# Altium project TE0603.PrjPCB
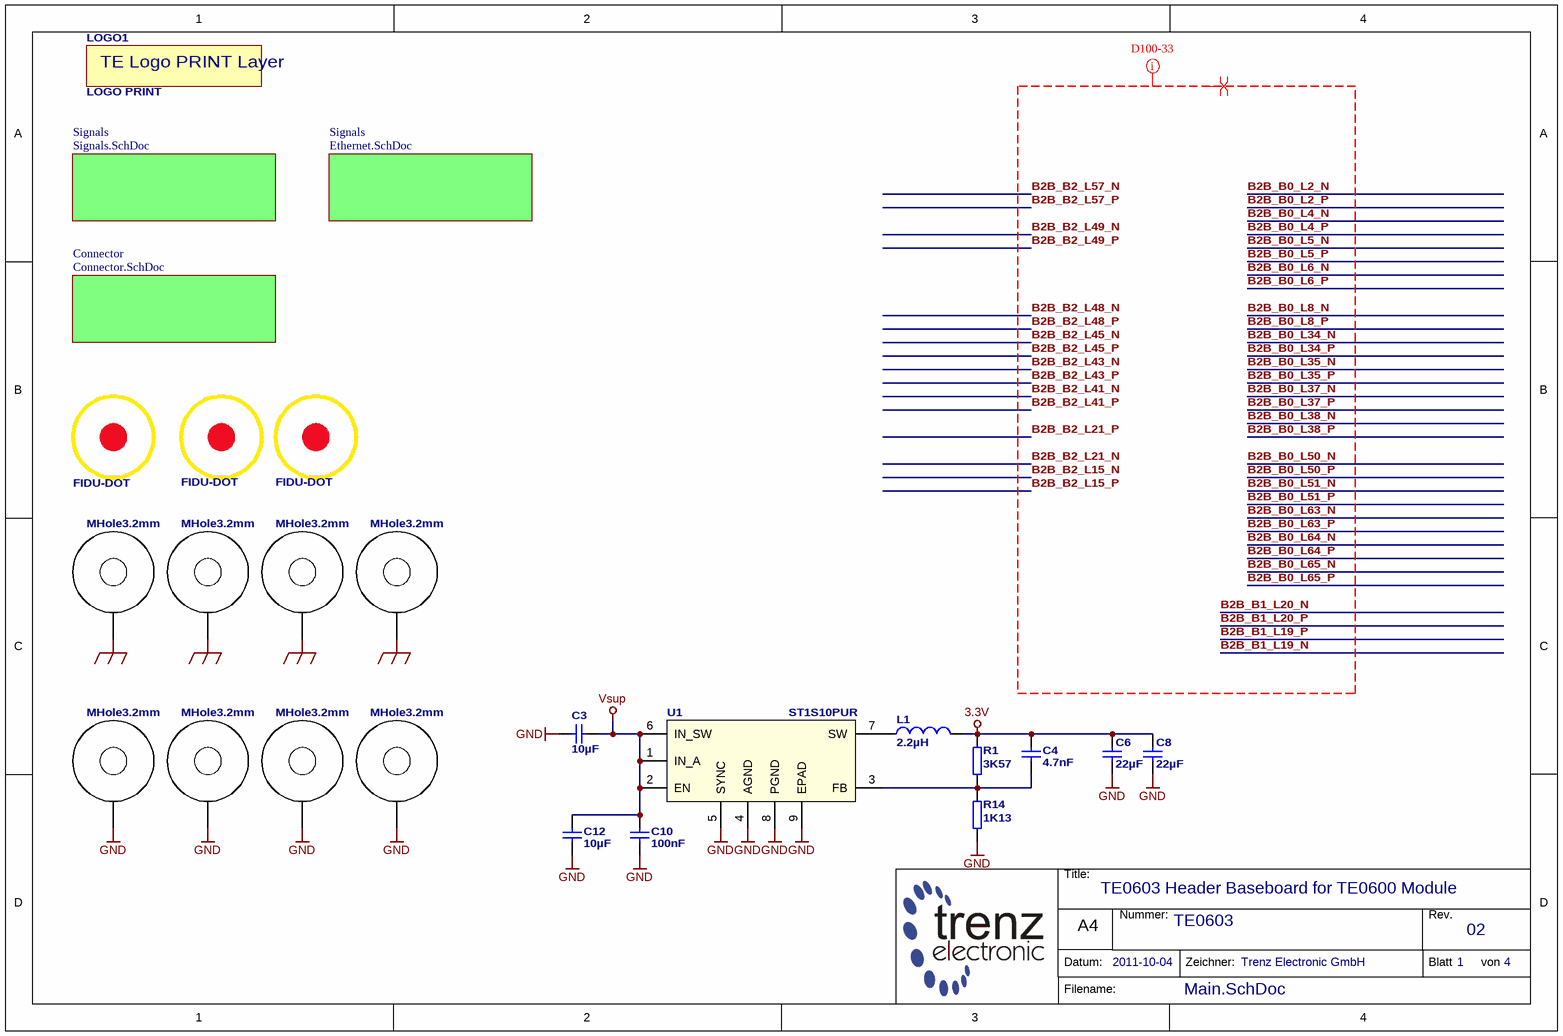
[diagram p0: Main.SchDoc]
4 sheets, 86 parts. Net scope: global (net labels, ports and power ports of the same name join across sheets).
Board file: TE0603.PcbDoc
Sheets:
  Main.SchDoc
    Connector = Connector.SchDoc
    Signals = Signals.SchDoc
    Signals = Ethernet.SchDoc

## Sheet Main.SchDoc: TE0603 Header Baseboard for TE0600 Module
size A4; Organization: Trenz Electronic GmbH; DocumentNumber: TE0603; Revision: 02; SheetNumber: 1; SheetTotal: 4; Date: 2011-10-04

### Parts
C3  10µF  [CAPC3225X279N]
C4  4.7nF  [CAPC1005X55N]
C6  22µF  [CAPC2012N]
C8  22µF  [CAPC2012N]
C10  100nF  [CAPC1608N]
C12  10µF  [CAPC3225X279N]
H1  MHole3.2mm  [MHole3_2mm]  (no BOM)
H2  MHole3.2mm  [MHole3_2mm]  (no BOM)
H3  MHole3.2mm  [MHole3_2mm]  (no BOM)
H4  MHole3.2mm  [MHole3_2mm]  (no BOM)
H5  MHole3.2mm  [MHole3_2mm]  (no BOM)
H6  MHole3.2mm  [MHole3_2mm]  (no BOM)
H7  MHole3.2mm  [MHole3_2mm]  (no BOM)
H8  MHole3.2mm  [MHole3_2mm]  (no BOM)
L1  2.2µH  [WE-PD-S-P]
LOGO1  LOGO PRINT  [LOGO PRINT]  (no BOM)
PM1  FIDU-DOT  [FIDU-DOT]
PM2  FIDU-DOT  [FIDU-DOT]
PM3  FIDU-DOT  [FIDU-DOT]
R1  3K57  [RESC1005N]
R14  1K13  [RESC1005N]
U1  ST1S10PUR  [SON80P400X400X100-9N]

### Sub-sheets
Connector = Connector.SchDoc: no entries
Signals = Signals.SchDoc: no entries
Signals = Ethernet.SchDoc: no entries

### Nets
3.3V: C4.1 C6.1 C8.1 L1.2 R1.1
FGND: H1.1 H2.1 H3.1 H4.1
GND: C3.1 C6.2 C8.2 C10.2 C12.1 H5.1 H6.1 H7.1 H8.1 R14.2 U1.4(AGND) U1.5(SYNC) U1.8(PGND) U1.9(EPAD)
Vsup: C3.2 C10.1 C12.2 U1.1(IN_A) U1.2(EN) U1.6(IN_SW)
NetC4_2: C4.2 R1.2 R14.1 U1.3(FB)
NetL1_1: L1.1 U1.7(SW)

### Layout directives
net class D100-33: B2B_B0_L2_N, B2B_B0_L2_P, B2B_B0_L4_N, B2B_B0_L4_P, B2B_B0_L5_N, B2B_B0_L5_P, B2B_B0_L6_N, B2B_B0_L6_P, B2B_B0_L8_N, B2B_B0_L8_P, B2B_B0_L34_N, B2B_B0_L34_P, B2B_B0_L35_N, B2B_B0_L35_P, B2B_B0_L37_N, B2B_B0_L37_P, B2B_B0_L38_N, B2B_B0_L38_P, B2B_B0_L50_N, B2B_B0_L50_P, B2B_B0_L51_N, B2B_B0_L51_P, B2B_B0_L63_N, B2B_B0_L63_P, B2B_B0_L64_N, B2B_B0_L64_P, B2B_B0_L65_N, B2B_B0_L65_P, B2B_B1_L19_N, B2B_B1_L19_P, B2B_B1_L20_N, B2B_B1_L20_P, B2B_B2_L15_N, B2B_B2_L15_P, B2B_B2_L21_N, B2B_B2_L21_P, B2B_B2_L41_N, B2B_B2_L41_P, B2B_B2_L43_N, B2B_B2_L43_P, B2B_B2_L45_N, B2B_B2_L45_P, B2B_B2_L48_N, B2B_B2_L48_P, B2B_B2_L49_N, B2B_B2_L49_P, B2B_B2_L57_N, B2B_B2_L57_P
differential pair: B2B_B0_L2_N, B2B_B0_L2_P, B2B_B0_L4_N, B2B_B0_L4_P, B2B_B0_L5_N, B2B_B0_L5_P, B2B_B0_L6_N, B2B_B0_L6_P, B2B_B0_L8_N, B2B_B0_L8_P, B2B_B0_L34_N, B2B_B0_L34_P, B2B_B0_L35_N, B2B_B0_L35_P, B2B_B0_L37_N, B2B_B0_L37_P, B2B_B0_L38_N, B2B_B0_L38_P, B2B_B0_L50_N, B2B_B0_L50_P, B2B_B0_L51_N, B2B_B0_L51_P, B2B_B0_L63_N, B2B_B0_L63_P, B2B_B0_L64_N, B2B_B0_L64_P, B2B_B0_L65_N, B2B_B0_L65_P, B2B_B1_L19_N, B2B_B1_L19_P, B2B_B1_L20_N, B2B_B1_L20_P, B2B_B2_L15_N, B2B_B2_L15_P, B2B_B2_L21_N, B2B_B2_L21_P, B2B_B2_L41_N, B2B_B2_L41_P, B2B_B2_L43_N, B2B_B2_L43_P, B2B_B2_L45_N, B2B_B2_L45_P, B2B_B2_L48_N, B2B_B2_L48_P, B2B_B2_L49_N, B2B_B2_L49_P, B2B_B2_L57_N, B2B_B2_L57_P

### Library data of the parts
C3 C12 = 23514: KON 10µF 50V  X5R SMD; AN: 23514; Value: 10u; Param 4: SMT
C4 = 22582: KON 4,7nF 50V X7R SMD; AN: 22582; Value: 4.7n; Param 4: SMT
C6 C8 = 23410: KON 22µF 6,3V  X5R SMD; AN: 23410; Param 1: 6.3V; Value: 22u; Param 4: SMT
C10 = 21382: KON 100nF 50V X7R SMD; AN: 21382; Value: 100n; Param 4: SMT
H1-H8 = 22898: AN: 22898
L1 = 22681: IND SMD 2,2µH IDC=4,02A, Isat=4,8A; AN: 22681; Param 1: 4.02A; Param 2: 0.02Ohm; Value: 2.2u; Param 4: SMT; Trenz-Stock: Yes
LOGO1 = 23748: AN: 23748
PM1-PM3 = 22906: AN: 22906
R1 = 23145: WID SMD 3K57 1% 0,063W; AN: 23145; Value: 3.57K; Param 4: SMT
R14 = 23160: WID SMD 1K13 1% 0,063W; AN: 23160; Value: 1.13K; Param 4: SMT
U1 = 23402: AN: 23402; Param 4: SMT; Trenz-Stock: Yes

## Sheet Connector.SchDoc: Header Baseboard - Headers
size A4; Organization: Trenz Electronic GmbH; DocumentNumber: TE0603; Revision: 02; SheetNumber: 2; SheetTotal: 4; Date: 2011-10-04; PageSetup: Record=PageOptions|CenterHorizontal=True|CenterVertical=True|PrintScale=2.81|XCorrection=1.00|YCorrection=1.00|PrintKind=0|BorderSize=5000000|LeftOffset=0|BottomOffset=0|Orientation=2|PaperLength=1000|PaperWidth=1000|Scale=100|PaperSource=7|PrintQuality=-4|MediaType=1|DitherType=10|PaperKind=A1 (594 x 841 mm)|PrintScaleMode=1
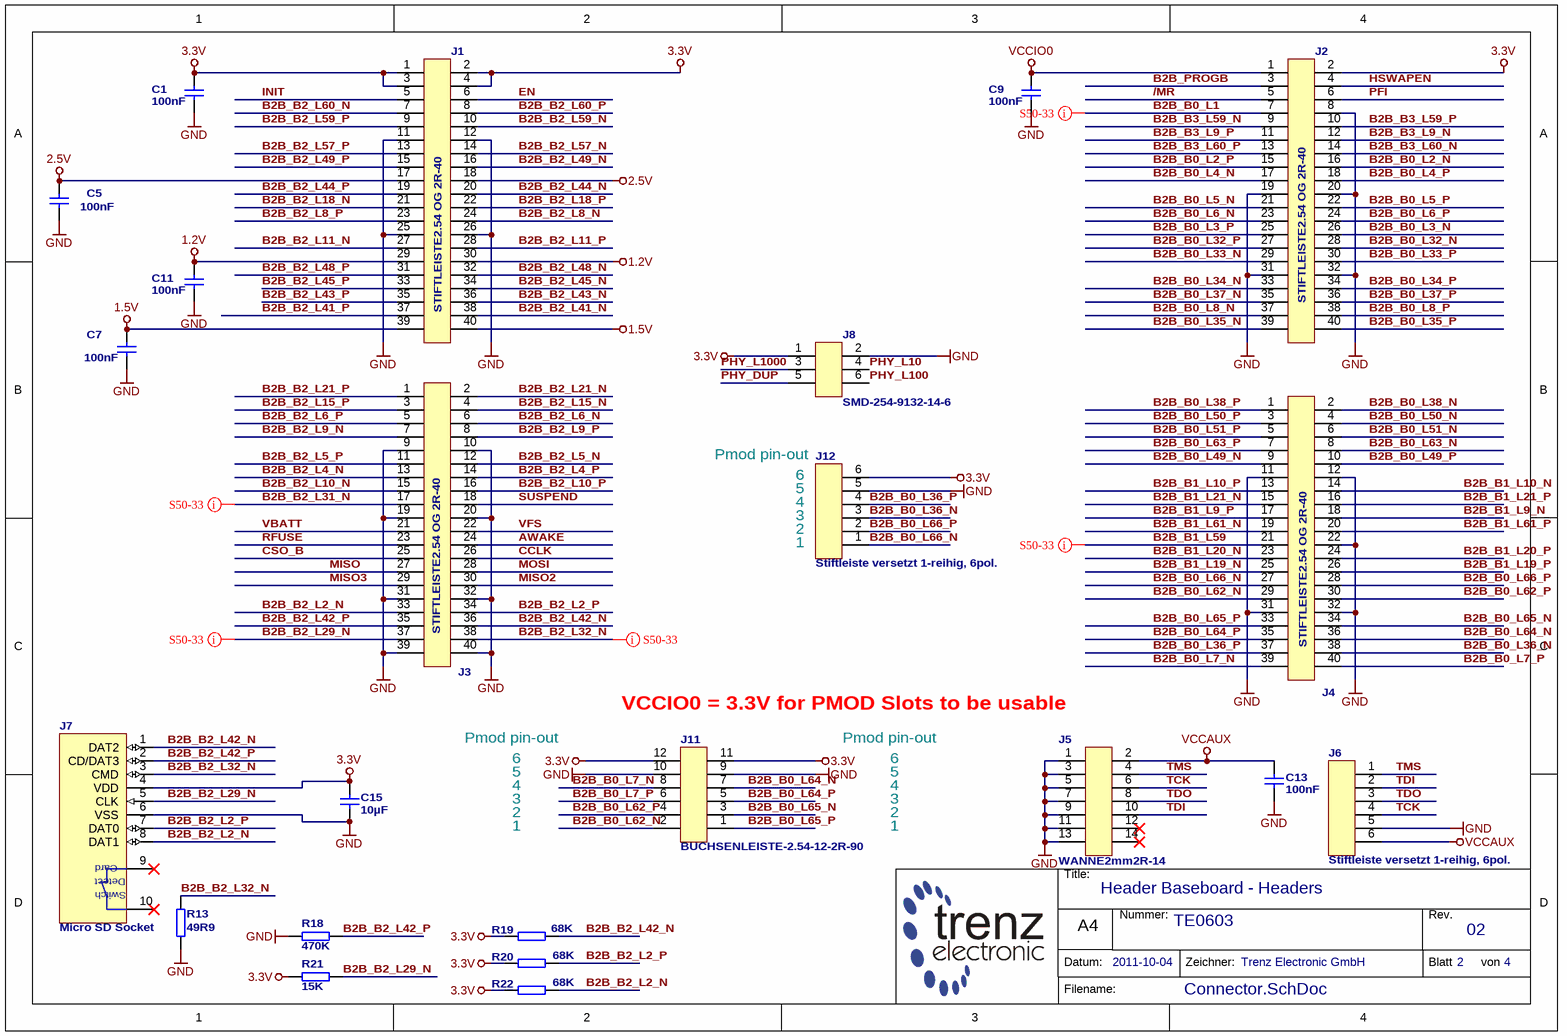
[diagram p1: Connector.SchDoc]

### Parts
C1  100nF  [CAPC1608N]
C5  100nF  [CAPC1608N]
C7  100nF  [CAPC1608N]
C9  100nF  [CAPC1608N]
C11  100nF  [CAPC1608N]
C13  100nF  [CAPC1608N]
C15  10µF  [CAPC1608N]
J1  STIFTLEISTE2.54 OG 2R-40  [STIFTLEISTE2_54 OG 2R-40]
J2  STIFTLEISTE2.54 OG 2R-40  [STIFTLEISTE2_54 OG 2R-40]
J3  STIFTLEISTE2.54 OG 2R-40  [STIFTLEISTE2_54 OG 2R-40]
J4  STIFTLEISTE2.54 OG 2R-40  [STIFTLEISTE2_54 OG 2R-40]
J5  WANNE2mm2R-14  [WANNE2mm2R-14]
J6  Stiftleiste versetzt 1-reihig, 6pol.  [STIFTLEISTE2_54 OG 1R-6V]
J7  Micro SD Socket  [112A-TXAR-R01]
J8  SMD-254-9132-14-6  [SMD-254-9132-14-6]
J11  BUCHSENLEISTE-2.54-12-2R-90  [BUCHSENLEISTE-2.54-12-2R-90]
J12  Stiftleiste versetzt 1-reihig, 6pol.  [STIFTLEISTE2_54 OG 1R-6V]
R13  49R9  [RESC1609N]
R18  470K  [RESC1609N]
R19  68K  [RESC1609N]
R20  68K  [RESC1609N]
R21  15K  [RESC1609N]
R22  68K  [RESC1609N]

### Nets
1.2V: C11.1 J1.29 J1.30
1.5V: C7.1 J1.39 J1.40
2.5V: C5.1 J1.17 J1.18
3.3V: C1.1 C15.1 J1.1 J1.2 J1.3 J1.4 J2.2 J7.4(VDD) J8.1 J11.11 J11.12 J12.6 R19.1 R20.1 R21.1 R22.1
GND: C1.2 C5.2 C7.2 C9.2 C11.2 C13.2 C15.2 J1.11 J1.12 J1.25 J1.26 J2.8 J2.19 J2.20 J2.31 J2.32 J3.9 J3.10 J3.19 J3.20 J3.31 J3.32 J3.39 J3.40 J4.11 J4.12 J4.22 J4.31 J4.32 J5.1 J5.3 J5.5 J5.7 J5.9 J5.11 J5.13 J6.5 J7.6(VSS) J8.2 J11.9 J11.10 J12.5 R13.2 R18.1
VCCAUX: C13.1 J5.2 J6.6
VCCIO0: C9.1 J2.1
/MR: J2.5
AWAKE: J3.24
B2B_B0_L1: J2.7
B2B_B0_L2_N: J2.16
B2B_B0_L2_P: J2.15
B2B_B0_L3_N: J2.26
B2B_B0_L3_P: J2.25
B2B_B0_L4_N: J2.17
B2B_B0_L4_P: J2.18
B2B_B0_L5_N: J2.21
B2B_B0_L5_P: J2.22
B2B_B0_L6_N: J2.23
B2B_B0_L6_P: J2.24
B2B_B0_L7_N: J4.39 J11.8
B2B_B0_L7_P: J4.40 J11.6
B2B_B0_L8_N: J2.37
B2B_B0_L8_P: J2.38
B2B_B0_L32_N: J2.28
B2B_B0_L32_P: J2.27
B2B_B0_L33_N: J2.29
B2B_B0_L33_P: J2.30
B2B_B0_L34_N: J2.33
B2B_B0_L34_P: J2.34
B2B_B0_L35_N: J2.39
B2B_B0_L35_P: J2.40
B2B_B0_L36_N: J4.38 J12.3
B2B_B0_L36_P: J4.37 J12.4
B2B_B0_L37_N: J2.35
B2B_B0_L37_P: J2.36
B2B_B0_L38_N: J4.2
B2B_B0_L38_P: J4.1
B2B_B0_L49_N: J4.9
B2B_B0_L49_P: J4.10
B2B_B0_L50_N: J4.4
B2B_B0_L50_P: J4.3
B2B_B0_L51_N: J4.6
B2B_B0_L51_P: J4.5
B2B_B0_L62_N: J4.29 J11.2
B2B_B0_L62_P: J4.30 J11.4
B2B_B0_L63_N: J4.8
B2B_B0_L63_P: J4.7
B2B_B0_L64_N: J4.36 J11.7
B2B_B0_L64_P: J4.35 J11.5
B2B_B0_L65_N: J4.34 J11.3
B2B_B0_L65_P: J4.33 J11.1
B2B_B0_L66_N: J4.27 J12.1
B2B_B0_L66_P: J4.28 J12.2
B2B_B1_L9_N: J4.18
B2B_B1_L9_P: J4.17
B2B_B1_L10_N: J4.14
B2B_B1_L10_P: J4.13
B2B_B1_L19_N: J4.25
B2B_B1_L19_P: J4.26
B2B_B1_L20_N: J4.23
B2B_B1_L20_P: J4.24
B2B_B1_L21_N: J4.15
B2B_B1_L21_P: J4.16
B2B_B1_L59: J4.21
B2B_B1_L61_N: J4.19
B2B_B1_L61_P: J4.20
B2B_B2_L2_N: J3.33 J7.8(DAT1) R22.2
B2B_B2_L2_P: J3.34 J7.7(DAT0) R20.2
B2B_B2_L4_N: J3.13
B2B_B2_L4_P: J3.14
B2B_B2_L5_N: J3.12
B2B_B2_L5_P: J3.11
B2B_B2_L6_N: J3.6
B2B_B2_L6_P: J3.5
B2B_B2_L8_N: J1.24
B2B_B2_L8_P: J1.23
B2B_B2_L9_N: J3.7
B2B_B2_L9_P: J3.8
B2B_B2_L10_N: J3.15
B2B_B2_L10_P: J3.16
B2B_B2_L11_N: J1.27
B2B_B2_L11_P: J1.28
B2B_B2_L15_N: J3.4
B2B_B2_L15_P: J3.3
B2B_B2_L18_N: J1.21
B2B_B2_L18_P: J1.22
B2B_B2_L21_N: J3.2
B2B_B2_L21_P: J3.1
B2B_B2_L29_N: J3.37 J7.5(CLK) R21.2
B2B_B2_L31_N: J3.17
B2B_B2_L32_N: J3.38 J7.3(CMD) R13.1
B2B_B2_L41_N: J1.38
B2B_B2_L41_P: J1.37
B2B_B2_L42_N: J3.36 J7.1(DAT2) R19.2
B2B_B2_L42_P: J3.35 J7.2(CD/DAT3) R18.2
B2B_B2_L43_N: J1.36
B2B_B2_L43_P: J1.35
B2B_B2_L44_N: J1.20
B2B_B2_L44_P: J1.19
B2B_B2_L45_N: J1.34
B2B_B2_L45_P: J1.33
B2B_B2_L48_N: J1.32
B2B_B2_L48_P: J1.31
B2B_B2_L49_N: J1.16
B2B_B2_L49_P: J1.15
B2B_B2_L57_N: J1.14
B2B_B2_L57_P: J1.13
B2B_B2_L59_N: J1.10
B2B_B2_L59_P: J1.9
B2B_B2_L60_N: J1.7
B2B_B2_L60_P: J1.8
B2B_B3_L9_N: J2.12
B2B_B3_L9_P: J2.11
B2B_B3_L59_N: J2.9
B2B_B3_L59_P: J2.10
B2B_B3_L60_N: J2.14
B2B_B3_L60_P: J2.13
B2B_PROGB: J2.3
CCLK: J3.26
CSO_B: J3.25
EN: J1.6
HSWAPEN: J2.4
INIT: J1.5
MISO: J3.27
MISO2: J3.30
MISO3: J3.29
MOSI: J3.28
PFI: J2.6
PHY_DUP: J8.5
PHY_L10: J8.4
PHY_L100: J8.6
PHY_L1000: J8.3
RFUSE: J3.23
SUSPEND: J3.18
TCK: J5.6 J6.4
TDI: J5.10 J6.2
TDO: J5.8 J6.3
TMS: J5.4 J6.1
VBATT: J3.21
VFS: J3.22

Not connected (* = marked no-connect by the designer): J5 12* 14*; J7 9* 10*

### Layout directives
net class S50-33: B2B_B0_L1, B2B_B1_L59, B2B_B2_L29_N, B2B_B2_L31_N, B2B_B2_L32_N

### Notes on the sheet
- Pmod pin-out
- (near J12) 3
- (near J12) 4
- (near J12) 5
- (near J12) 6
- (near J12) 1
- (near J12) 2
- (near J11) VCCIO0 = 3.3V for PMOD Slots to be usable
- 4
- 5
- 6
- 1
- 2
- 3

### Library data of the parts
C1 C5 C7 C9 C11 C13 = 21382: as C10 on sheet Main
C15 = 22918: KON 10µF 6,3V X7R SMD; AN: 22918; Param 1: 6.3V; Value: 10u; Param 4: SMT
J1-J4 = 22320: Stiftleiste gerade 2-reihig, 40pol; AN: 22320; Trenz-Stock: Yes
J5 = 22744: Stiftleiste Wanne 14polig SMD; AN: 22744; Param 4: SMT; Trenz-Stock: Yes
J6 J12 = 22911: AN: 22911; Trenz-Stock: Yes
J7 = 23193: AN: 23193; Param 4: SMT; Trenz-Stock: Yes
J8 = 22742: Stiftleiste gerade 2reihig, 6pol. SMD; AN: 22742; Param 4: SMT; Trenz-Stock: Yes
J11 = 23185: Buchsenleiste 2-reihig, 12pol 90°; AN: 23185; Trenz-Stock: Yes
R13 = 22534: WID SMD 49R9 1% 0,1W; AN: 22534; Value: 49.9; Param 4: SMT
R18 = 21523: WID SMD 470K 1% 0,1W; AN: 21523; Param 4: SMT
R19 R20 R22 = 22531: WID SMD 68K 1% 0,1W; AN: 22531; Param 4: SMT
R21 = 22528: WID SMD 15K 1% 0,1W; AN: 22528; Param 4: SMT

## Sheet Signals.SchDoc: Header Baseboard - B2B connectors
size A4; Organization: Trenz Electronic GmbH; DocumentNumber: TE0603; Revision: 02; SheetNumber: 4; SheetTotal: 4; Date: 2011-10-04; PageSetup: Record=PageOptions|CenterHorizontal=True|CenterVertical=True|PrintScale=2.81|XCorrection=1.00|YCorrection=1.00|PrintKind=0|BorderSize=5000000|LeftOffset=0|BottomOffset=0|Orientation=2|PaperLength=1000|PaperWidth=1000|Scale=100|PaperSource=7|PrintQuality=-4|MediaType=1|DitherType=10|PaperKind=A1 (594 x 841 mm)|PrintScaleMode=1
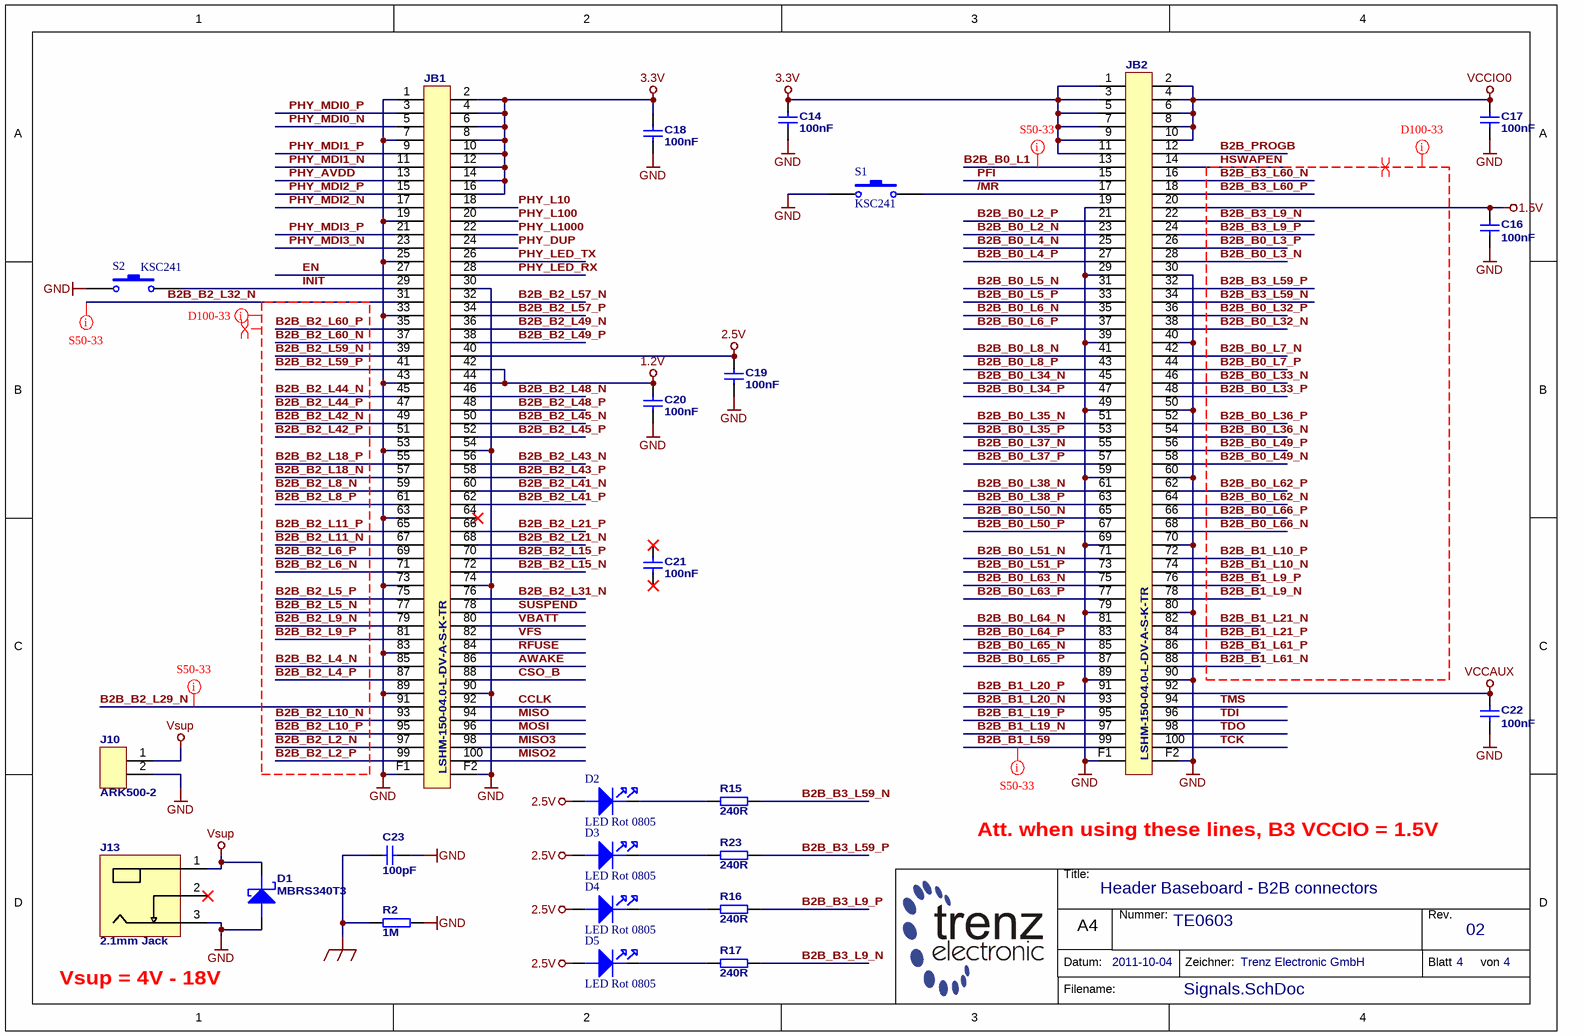
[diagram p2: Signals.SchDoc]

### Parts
C14  100nF  [CAPC1608N]
C16  100nF  [CAPC1608N]
C17  100nF  [CAPC1608N]
C18  100nF  [CAPC1608N]
C19  100nF  [CAPC1608N]
C20  100nF  [CAPC1608N]
C21  100nF  [CAPC1608N]
C22  100nF  [CAPC1608N]
C23  100pF  [CAPC3216N]
D1  MBRS340T3  [MBRS340T3]
D2  LED Rot 0805  [OLD_LED805]
D3  LED Rot 0805  [OLD_LED805]
D4  LED Rot 0805  [OLD_LED805]
D5  LED Rot 0805  [OLD_LED805]
J10  ARK500-2  [ARK500-2]
J13  2.1mm Jack  [WS-DC001]
JB1  LSHM-150-04.0-L-DV-A-S-K-TR  [LSHM-150-XXX-X-DV-A-X]
JB2  LSHM-150-04.0-L-DV-A-S-K-TR  [LSHM-150-XXX-X-DV-A-X]
R2  1M  [RESC3216N]
R15  240R  [RESC1609N]
R16  240R  [RESC1609N]
R17  240R  [RESC1609N]
R23  240R  [RESC1609N]
S1  KSC241  [DTSM61N]
S2  KSC241  [DTSM61N]

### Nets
1.2V: C20.2 JB1.42 JB1.44
1.5V: C16.1 JB2.20
2.5V: C19.2 D2.A D3.A D4.A D5.A JB1.40
3.3V: C14.1 C18.2 JB1.2 JB1.4 JB1.6 JB1.8 JB1.10 JB1.12 JB1.14 JB1.16 JB2.1 JB2.3 JB2.5 JB2.7 JB2.9 JB2.11
FGND: C23.1 R2.1
GND: C14.2 C16.2 C17.2 C18.1 C19.1 C20.1 C22.2 C23.2 D1.2(ANODE) J10.2 J13.3 JB1.1 JB1.7 JB1.19 JB1.25 JB1.30 JB1.33 JB1.43 JB1.53 JB1.54 JB1.63 JB1.73 JB1.74 JB1.83 JB1.89 JB1.90 JB1.F1(Shield) JB1.F2(Shield) JB2.19 JB2.29 JB2.30 JB2.39 JB2.40 JB2.49 JB2.50 JB2.59 JB2.60 JB2.69 JB2.70 JB2.79 JB2.80 JB2.89 JB2.90 JB2.F1(Shield) JB2.F2(Shield) R2.2 S1.2 S2.2
VCCAUX: C22.1 JB2.92
VCCIO0: C17.1 JB2.2 JB2.4 JB2.6 JB2.8 JB2.10
Vsup: D1.1(CATHODE) J10.1 J13.1
/MR: JB2.17 S1.1
AWAKE: JB1.86
B2B_B0_L1: JB2.13
B2B_B0_L2_N: JB2.23
B2B_B0_L2_P: JB2.21
B2B_B0_L3_N: JB2.28
B2B_B0_L3_P: JB2.26
B2B_B0_L4_N: JB2.25
B2B_B0_L4_P: JB2.27
B2B_B0_L5_N: JB2.31
B2B_B0_L5_P: JB2.33
B2B_B0_L6_N: JB2.35
B2B_B0_L6_P: JB2.37
B2B_B0_L7_N: JB2.42
B2B_B0_L7_P: JB2.44
B2B_B0_L8_N: JB2.41
B2B_B0_L8_P: JB2.43
B2B_B0_L32_N: JB2.38
B2B_B0_L32_P: JB2.36
B2B_B0_L33_N: JB2.46
B2B_B0_L33_P: JB2.48
B2B_B0_L34_N: JB2.45
B2B_B0_L34_P: JB2.47
B2B_B0_L35_N: JB2.51
B2B_B0_L35_P: JB2.53
B2B_B0_L36_N: JB2.54
B2B_B0_L36_P: JB2.52
B2B_B0_L37_N: JB2.55
B2B_B0_L37_P: JB2.57
B2B_B0_L38_N: JB2.61
B2B_B0_L38_P: JB2.63
B2B_B0_L49_N: JB2.58
B2B_B0_L49_P: JB2.56
B2B_B0_L50_N: JB2.65
B2B_B0_L50_P: JB2.67
B2B_B0_L51_N: JB2.71
B2B_B0_L51_P: JB2.73
B2B_B0_L62_N: JB2.64
B2B_B0_L62_P: JB2.62
B2B_B0_L63_N: JB2.75
B2B_B0_L63_P: JB2.77
B2B_B0_L64_N: JB2.81
B2B_B0_L64_P: JB2.83
B2B_B0_L65_N: JB2.85
B2B_B0_L65_P: JB2.87
B2B_B0_L66_N: JB2.68
B2B_B0_L66_P: JB2.66
B2B_B1_L9_N: JB2.78
B2B_B1_L9_P: JB2.76
B2B_B1_L10_N: JB2.74
B2B_B1_L10_P: JB2.72
B2B_B1_L19_N: JB2.97
B2B_B1_L19_P: JB2.95
B2B_B1_L20_N: JB2.93
B2B_B1_L20_P: JB2.91
B2B_B1_L21_N: JB2.82
B2B_B1_L21_P: JB2.84
B2B_B1_L59: JB2.99
B2B_B1_L61_N: JB2.88
B2B_B1_L61_P: JB2.86
B2B_B2_L2_N: JB1.97
B2B_B2_L2_P: JB1.99
B2B_B2_L4_N: JB1.85
B2B_B2_L4_P: JB1.87
B2B_B2_L5_N: JB1.77
B2B_B2_L5_P: JB1.75
B2B_B2_L6_N: JB1.71
B2B_B2_L6_P: JB1.69
B2B_B2_L8_N: JB1.59
B2B_B2_L8_P: JB1.61
B2B_B2_L9_N: JB1.79
B2B_B2_L9_P: JB1.81
B2B_B2_L10_N: JB1.93
B2B_B2_L10_P: JB1.95
B2B_B2_L11_N: JB1.67
B2B_B2_L11_P: JB1.65
B2B_B2_L15_N: JB1.72
B2B_B2_L15_P: JB1.70
B2B_B2_L18_N: JB1.57
B2B_B2_L18_P: JB1.55
B2B_B2_L21_N: JB1.68
B2B_B2_L21_P: JB1.66
B2B_B2_L29_N: JB1.91
B2B_B2_L31_N: JB1.76
B2B_B2_L32_N: JB1.31
B2B_B2_L41_N: JB1.60
B2B_B2_L41_P: JB1.62
B2B_B2_L42_N: JB1.49
B2B_B2_L42_P: JB1.51
B2B_B2_L43_N: JB1.56
B2B_B2_L43_P: JB1.58
B2B_B2_L44_N: JB1.45
B2B_B2_L44_P: JB1.47
B2B_B2_L45_N: JB1.50
B2B_B2_L45_P: JB1.52
B2B_B2_L48_N: JB1.46
B2B_B2_L48_P: JB1.48
B2B_B2_L49_N: JB1.36
B2B_B2_L49_P: JB1.38
B2B_B2_L57_N: JB1.32
B2B_B2_L57_P: JB1.34
B2B_B2_L59_N: JB1.39
B2B_B2_L59_P: JB1.41
B2B_B2_L60_N: JB1.37
B2B_B2_L60_P: JB1.35
B2B_B3_L9_N: JB2.22 R17.2
B2B_B3_L9_P: JB2.24 R16.2
B2B_B3_L59_N: JB2.34 R15.2
B2B_B3_L59_P: JB2.32 R23.2
B2B_B3_L60_N: JB2.16
B2B_B3_L60_P: JB2.18
B2B_PROGB: JB2.12
CCLK: JB1.92
CSO_B: JB1.88
EN: JB1.27
HSWAPEN: JB2.14
INIT: JB1.29 S2.1
MISO: JB1.94
MISO2: JB1.100
MISO3: JB1.98
MOSI: JB1.96
PFI: JB2.15
PHY_AVDD: JB1.13
PHY_DUP: JB1.24
PHY_L10: JB1.18
PHY_L100: JB1.20
PHY_L1000: JB1.22
PHY_LED_RX: JB1.28
PHY_LED_TX: JB1.26
PHY_MDI0_N: JB1.5
PHY_MDI0_P: JB1.3
PHY_MDI1_N: JB1.11
PHY_MDI1_P: JB1.9
PHY_MDI2_N: JB1.17
PHY_MDI2_P: JB1.15
PHY_MDI3_N: JB1.23
PHY_MDI3_P: JB1.21
RFUSE: JB1.84
SUSPEND: JB1.78
TCK: JB2.100
TDI: JB2.96
TDO: JB2.98
TMS: JB2.94
VBATT: JB1.80
VFS: JB1.82
NetD2_K: D2.K R15.1
NetD3_K: D3.K R23.1
NetD4_K: D4.K R16.1
NetD5_K: D5.K R17.1

Not connected (* = marked no-connect by the designer): C21 1* 2*; J13 2*; JB1 64*

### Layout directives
net class S50-33: B2B_B0_L1, B2B_B1_L59, B2B_B2_L29_N, B2B_B2_L32_N
net class D100-33: B2B_B0_L3_N, B2B_B0_L3_P, B2B_B0_L7_N, B2B_B0_L7_P, B2B_B0_L32_N, B2B_B0_L32_P, B2B_B0_L33_N, B2B_B0_L33_P, B2B_B0_L36_N, B2B_B0_L36_P, B2B_B0_L49_N, B2B_B0_L49_P, B2B_B0_L62_N, B2B_B0_L62_P, B2B_B0_L66_N, B2B_B0_L66_P, B2B_B1_L9_N, B2B_B1_L9_P, B2B_B1_L10_N, B2B_B1_L10_P, B2B_B1_L21_N, B2B_B1_L21_P, B2B_B1_L61_N, B2B_B1_L61_P, B2B_B2_L2_N, B2B_B2_L2_P, B2B_B2_L4_N, B2B_B2_L4_P, B2B_B2_L5_N, B2B_B2_L5_P, B2B_B2_L6_N, B2B_B2_L6_P, B2B_B2_L8_N, B2B_B2_L8_P, B2B_B2_L9_N, B2B_B2_L9_P, B2B_B2_L10_N, B2B_B2_L10_P, B2B_B2_L11_N, B2B_B2_L11_P, B2B_B2_L18_N, B2B_B2_L18_P, B2B_B2_L42_N, B2B_B2_L42_P, B2B_B2_L44_N, B2B_B2_L44_P, B2B_B2_L59_N, B2B_B2_L59_P, B2B_B2_L60_N, B2B_B2_L60_P, B2B_B3_L9_N, B2B_B3_L9_P, B2B_B3_L59_N, B2B_B3_L59_P, B2B_B3_L60_N, B2B_B3_L60_P, HSWAPEN
differential pair: B2B_B0_L3_N, B2B_B0_L3_P, B2B_B0_L7_N, B2B_B0_L7_P, B2B_B0_L32_N, B2B_B0_L32_P, B2B_B0_L33_N, B2B_B0_L33_P, B2B_B0_L36_N, B2B_B0_L36_P, B2B_B0_L49_N, B2B_B0_L49_P, B2B_B0_L62_N, B2B_B0_L62_P, B2B_B0_L66_N, B2B_B0_L66_P, B2B_B1_L9_N, B2B_B1_L9_P, B2B_B1_L10_N, B2B_B1_L10_P, B2B_B1_L21_N, B2B_B1_L21_P, B2B_B1_L61_N, B2B_B1_L61_P, B2B_B2_L2_N, B2B_B2_L2_P, B2B_B2_L4_N, B2B_B2_L4_P, B2B_B2_L5_N, B2B_B2_L5_P, B2B_B2_L6_N, B2B_B2_L6_P, B2B_B2_L8_N, B2B_B2_L8_P, B2B_B2_L9_N, B2B_B2_L9_P, B2B_B2_L10_N, B2B_B2_L10_P, B2B_B2_L11_N, B2B_B2_L11_P, B2B_B2_L18_N, B2B_B2_L18_P, B2B_B2_L42_N, B2B_B2_L42_P, B2B_B2_L44_N, B2B_B2_L44_P, B2B_B2_L59_N, B2B_B2_L59_P, B2B_B2_L60_N, B2B_B2_L60_P, B2B_B3_L9_N, B2B_B3_L9_P, B2B_B3_L59_N, B2B_B3_L59_P, B2B_B3_L60_N, B2B_B3_L60_P, HSWAPEN

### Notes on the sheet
- Att. when using these lines, B3 VCCIO = 1.5V
- (near J13) Vsup = 4V - 18V

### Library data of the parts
C14 C16-C22 = 21382: as C10 on sheet Main
C23 = 22679: KON 100pF X7R; AN: 22679; Value: 100p
D1 = 22887: MBRS340T3 SMD; AN: 22887; Param 4: SMT
D2-D5 = 24266: LED Rot BL-HE135A-AV-TRB SMD obsolete; AN: 24266; Param 4: SMT
J10 = 20123: Schraubklemme LP 2 pol ARK500-2; AN: 20123; Trenz-Stock: Yes
J13 = 22832: STE 2,1mm Buchse; AN: 22832; Trenz-Stock: Yes
JB1 JB2 = 23838: STE B2B 100 Pol. 0,5mm 4,0mm; AN: 23838; Param 4: SMT; Trenz-Stock: Yes
R2 = 22757: WID SMD 1M; AN: 22757; Param 4: SMT
R15-R17 R23 = 23598: WID SMD 240R 1% 0,1W; AN: 23598; Value: 240; Param 4: SMT
S1 S2 = 24277: Taster Miniatur Leiterplatte 3N; AN: 24277; Param 4: SMT

## Sheet Ethernet.SchDoc: Ethernet
size A4; Date: 2011-10-04; Organization: Trenz Electronic GmbH; DocumentNumber: TE0603; Revision: 02; SheetNumber: 3; SheetTotal: 4
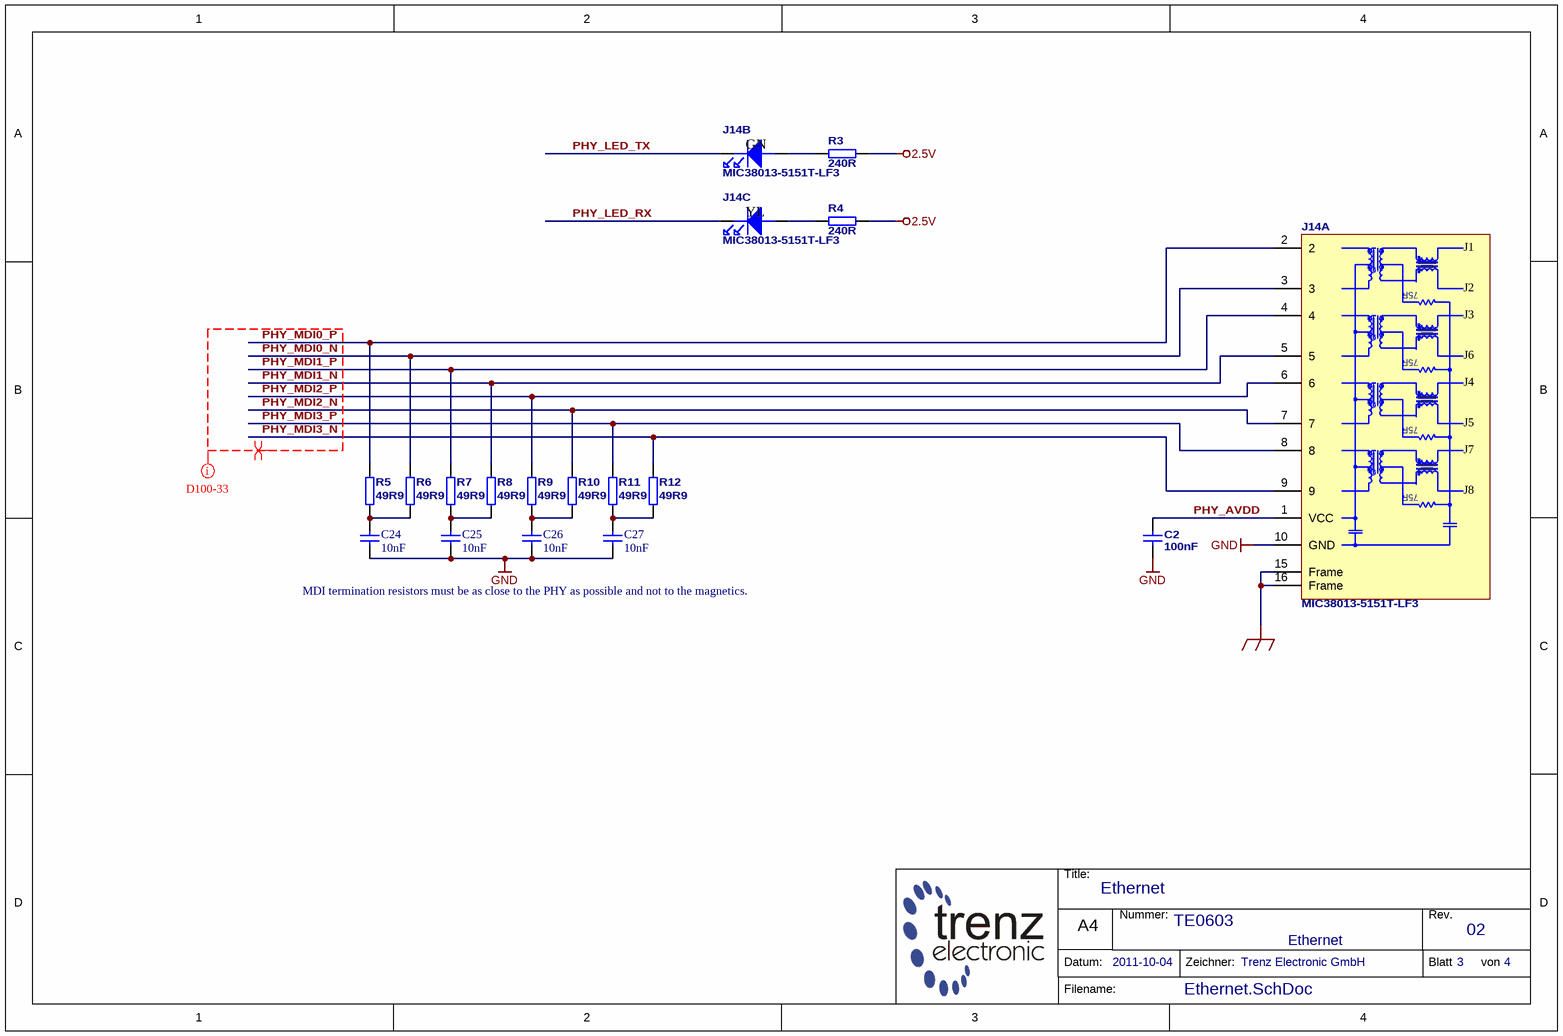
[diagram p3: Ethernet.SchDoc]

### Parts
C2  100nF  [CAPC1608N]
C24  10nF  [CAPC1608N]
C25  10nF  [CAPC1608N]
C26  10nF  [CAPC1608N]
C27  10nF  [CAPC1608N]
J14  MIC38013-5151T-LF3  [MIC38013-5151T-LF3]  (parts A,B,C of 3)
R3  240R  [RESC1609N]
R4  240R  [RESC1609N]
R5  49R9  [RESC1609N]
R6  49R9  [RESC1609N]
R7  49R9  [RESC1609N]
R8  49R9  [RESC1609N]
R9  49R9  [RESC1609N]
R10  49R9  [RESC1609N]
R11  49R9  [RESC1609N]
R12  49R9  [RESC1609N]

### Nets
2.5V: R3.2 R4.2
FGND: J14.15(Frame) J14.16(Frame)
GND: C2.1 C24.2 C25.2 C26.2 C27.2 J14.10(GND)
PHY_AVDD: C2.2 J14.1(VCC)
PHY_LED_RX: J14.14(K)
PHY_LED_TX: J14.12(K)
PHY_MDI0_N: J14.3 R6.1
PHY_MDI0_P: J14.2 R5.1
PHY_MDI1_N: J14.5 R8.1
PHY_MDI1_P: J14.4 R7.1
PHY_MDI2_N: J14.7 R10.1
PHY_MDI2_P: J14.6 R9.1
PHY_MDI3_N: J14.9 R12.1
PHY_MDI3_P: J14.8 R11.1
NetC24_1: C24.1 R5.2 R6.2
NetC25_1: C25.1 R7.2 R8.2
NetC26_1: C26.1 R9.2 R10.2
NetC27_1: C27.1 R11.2 R12.2
NetJ14_11: J14.11(A) R3.1
NetJ14_13: J14.13(A) R4.1

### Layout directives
differential pair: PHY_MDI0_N, PHY_MDI0_P, PHY_MDI1_N, PHY_MDI1_P, PHY_MDI2_N, PHY_MDI2_P, PHY_MDI3_N, PHY_MDI3_P
net class D100-33: PHY_MDI0_N, PHY_MDI0_P, PHY_MDI1_N, PHY_MDI1_P, PHY_MDI2_N, PHY_MDI2_P, PHY_MDI3_N, PHY_MDI3_P

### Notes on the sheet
- MDI termination resistors must be as close to the PHY as possible and not to the magnetics.

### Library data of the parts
C2 = 21382: as C10 on sheet Main
C24-C27 = 23774: KON 10nF 50V X7R SMD; AN: 23774; Value: 10n; Param 4: SMT
J14 = 23772: AN: 23772; Param 4: THT; Trenz-Stock: Yes
R3 R4 = 23598: as R15 on sheet Signals
R5-R12 = 22534: as R13 on sheet Connector

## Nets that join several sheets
1.2V: Connector (C11.1 J1.29 J1.30), Signals (C20.2 JB1.42 JB1.44)
1.5V: Connector (C7.1 J1.39 J1.40), Signals (C16.1 JB2.20)
2.5V: Connector (C5.1 J1.17 J1.18), Signals (6 pins), Ethernet (R3.2 R4.2)
3.3V: Main (5 pins), Connector (16 pins), Signals (16 pins)
FGND: Main (H1.1 H2.1 H3.1 H4.1), Signals (C23.1 R2.1), Ethernet (J14.15 J14.16)
GND: Main (14 pins), Connector (44 pins), Signals (48 pins), Ethernet (6 pins)
VCCAUX: Connector (C13.1 J5.2 J6.6), Signals (C22.1 JB2.92)
VCCIO0: Connector (C9.1 J2.1), Signals (6 pins)
Vsup: Main (6 pins), Signals (D1.1 J10.1 J13.1)
/MR: Connector (J2.5), Signals (JB2.17 S1.1)
AWAKE: Connector (J3.24), Signals (JB1.86)
B2B_B0_L1: Connector (J2.7), Signals (JB2.13)
B2B_B0_L2_N: Connector (J2.16), Signals (JB2.23)
B2B_B0_L2_P: Connector (J2.15), Signals (JB2.21)
B2B_B0_L3_N: Connector (J2.26), Signals (JB2.28)
B2B_B0_L3_P: Connector (J2.25), Signals (JB2.26)
B2B_B0_L4_N: Connector (J2.17), Signals (JB2.25)
B2B_B0_L4_P: Connector (J2.18), Signals (JB2.27)
B2B_B0_L5_N: Connector (J2.21), Signals (JB2.31)
B2B_B0_L5_P: Connector (J2.22), Signals (JB2.33)
B2B_B0_L6_N: Connector (J2.23), Signals (JB2.35)
B2B_B0_L6_P: Connector (J2.24), Signals (JB2.37)
B2B_B0_L7_N: Connector (J4.39 J11.8), Signals (JB2.42)
B2B_B0_L7_P: Connector (J4.40 J11.6), Signals (JB2.44)
B2B_B0_L8_N: Connector (J2.37), Signals (JB2.41)
B2B_B0_L8_P: Connector (J2.38), Signals (JB2.43)
B2B_B0_L32_N: Connector (J2.28), Signals (JB2.38)
B2B_B0_L32_P: Connector (J2.27), Signals (JB2.36)
B2B_B0_L33_N: Connector (J2.29), Signals (JB2.46)
B2B_B0_L33_P: Connector (J2.30), Signals (JB2.48)
B2B_B0_L34_N: Connector (J2.33), Signals (JB2.45)
B2B_B0_L34_P: Connector (J2.34), Signals (JB2.47)
B2B_B0_L35_N: Connector (J2.39), Signals (JB2.51)
B2B_B0_L35_P: Connector (J2.40), Signals (JB2.53)
B2B_B0_L36_N: Connector (J4.38 J12.3), Signals (JB2.54)
B2B_B0_L36_P: Connector (J4.37 J12.4), Signals (JB2.52)
B2B_B0_L37_N: Connector (J2.35), Signals (JB2.55)
B2B_B0_L37_P: Connector (J2.36), Signals (JB2.57)
B2B_B0_L38_N: Connector (J4.2), Signals (JB2.61)
B2B_B0_L38_P: Connector (J4.1), Signals (JB2.63)
B2B_B0_L49_N: Connector (J4.9), Signals (JB2.58)
B2B_B0_L49_P: Connector (J4.10), Signals (JB2.56)
B2B_B0_L50_N: Connector (J4.4), Signals (JB2.65)
B2B_B0_L50_P: Connector (J4.3), Signals (JB2.67)
B2B_B0_L51_N: Connector (J4.6), Signals (JB2.71)
B2B_B0_L51_P: Connector (J4.5), Signals (JB2.73)
B2B_B0_L62_N: Connector (J4.29 J11.2), Signals (JB2.64)
B2B_B0_L62_P: Connector (J4.30 J11.4), Signals (JB2.62)
B2B_B0_L63_N: Connector (J4.8), Signals (JB2.75)
B2B_B0_L63_P: Connector (J4.7), Signals (JB2.77)
B2B_B0_L64_N: Connector (J4.36 J11.7), Signals (JB2.81)
B2B_B0_L64_P: Connector (J4.35 J11.5), Signals (JB2.83)
B2B_B0_L65_N: Connector (J4.34 J11.3), Signals (JB2.85)
B2B_B0_L65_P: Connector (J4.33 J11.1), Signals (JB2.87)
B2B_B0_L66_N: Connector (J4.27 J12.1), Signals (JB2.68)
B2B_B0_L66_P: Connector (J4.28 J12.2), Signals (JB2.66)
B2B_B1_L9_N: Connector (J4.18), Signals (JB2.78)
B2B_B1_L9_P: Connector (J4.17), Signals (JB2.76)
B2B_B1_L10_N: Connector (J4.14), Signals (JB2.74)
B2B_B1_L10_P: Connector (J4.13), Signals (JB2.72)
B2B_B1_L19_N: Connector (J4.25), Signals (JB2.97)
B2B_B1_L19_P: Connector (J4.26), Signals (JB2.95)
B2B_B1_L20_N: Connector (J4.23), Signals (JB2.93)
B2B_B1_L20_P: Connector (J4.24), Signals (JB2.91)
B2B_B1_L21_N: Connector (J4.15), Signals (JB2.82)
B2B_B1_L21_P: Connector (J4.16), Signals (JB2.84)
B2B_B1_L59: Connector (J4.21), Signals (JB2.99)
B2B_B1_L61_N: Connector (J4.19), Signals (JB2.88)
B2B_B1_L61_P: Connector (J4.20), Signals (JB2.86)
B2B_B2_L2_N: Connector (J3.33 J7.8 R22.2), Signals (JB1.97)
B2B_B2_L2_P: Connector (J3.34 J7.7 R20.2), Signals (JB1.99)
B2B_B2_L4_N: Connector (J3.13), Signals (JB1.85)
B2B_B2_L4_P: Connector (J3.14), Signals (JB1.87)
B2B_B2_L5_N: Connector (J3.12), Signals (JB1.77)
B2B_B2_L5_P: Connector (J3.11), Signals (JB1.75)
B2B_B2_L6_N: Connector (J3.6), Signals (JB1.71)
B2B_B2_L6_P: Connector (J3.5), Signals (JB1.69)
B2B_B2_L8_N: Connector (J1.24), Signals (JB1.59)
B2B_B2_L8_P: Connector (J1.23), Signals (JB1.61)
B2B_B2_L9_N: Connector (J3.7), Signals (JB1.79)
B2B_B2_L9_P: Connector (J3.8), Signals (JB1.81)
B2B_B2_L10_N: Connector (J3.15), Signals (JB1.93)
B2B_B2_L10_P: Connector (J3.16), Signals (JB1.95)
B2B_B2_L11_N: Connector (J1.27), Signals (JB1.67)
B2B_B2_L11_P: Connector (J1.28), Signals (JB1.65)
B2B_B2_L15_N: Connector (J3.4), Signals (JB1.72)
B2B_B2_L15_P: Connector (J3.3), Signals (JB1.70)
B2B_B2_L18_N: Connector (J1.21), Signals (JB1.57)
B2B_B2_L18_P: Connector (J1.22), Signals (JB1.55)
B2B_B2_L21_N: Connector (J3.2), Signals (JB1.68)
B2B_B2_L21_P: Connector (J3.1), Signals (JB1.66)
B2B_B2_L29_N: Connector (J3.37 J7.5 R21.2), Signals (JB1.91)
B2B_B2_L31_N: Connector (J3.17), Signals (JB1.76)
B2B_B2_L32_N: Connector (J3.38 J7.3 R13.1), Signals (JB1.31)
B2B_B2_L41_N: Connector (J1.38), Signals (JB1.60)
B2B_B2_L41_P: Connector (J1.37), Signals (JB1.62)
B2B_B2_L42_N: Connector (J3.36 J7.1 R19.2), Signals (JB1.49)
B2B_B2_L42_P: Connector (J3.35 J7.2 R18.2), Signals (JB1.51)
B2B_B2_L43_N: Connector (J1.36), Signals (JB1.56)
B2B_B2_L43_P: Connector (J1.35), Signals (JB1.58)
B2B_B2_L44_N: Connector (J1.20), Signals (JB1.45)
B2B_B2_L44_P: Connector (J1.19), Signals (JB1.47)
B2B_B2_L45_N: Connector (J1.34), Signals (JB1.50)
B2B_B2_L45_P: Connector (J1.33), Signals (JB1.52)
B2B_B2_L48_N: Connector (J1.32), Signals (JB1.46)
B2B_B2_L48_P: Connector (J1.31), Signals (JB1.48)
B2B_B2_L49_N: Connector (J1.16), Signals (JB1.36)
B2B_B2_L49_P: Connector (J1.15), Signals (JB1.38)
B2B_B2_L57_N: Connector (J1.14), Signals (JB1.32)
B2B_B2_L57_P: Connector (J1.13), Signals (JB1.34)
B2B_B2_L59_N: Connector (J1.10), Signals (JB1.39)
B2B_B2_L59_P: Connector (J1.9), Signals (JB1.41)
B2B_B2_L60_N: Connector (J1.7), Signals (JB1.37)
B2B_B2_L60_P: Connector (J1.8), Signals (JB1.35)
B2B_B3_L9_N: Connector (J2.12), Signals (JB2.22 R17.2)
B2B_B3_L9_P: Connector (J2.11), Signals (JB2.24 R16.2)
B2B_B3_L59_N: Connector (J2.9), Signals (JB2.34 R15.2)
B2B_B3_L59_P: Connector (J2.10), Signals (JB2.32 R23.2)
B2B_B3_L60_N: Connector (J2.14), Signals (JB2.16)
B2B_B3_L60_P: Connector (J2.13), Signals (JB2.18)
B2B_PROGB: Connector (J2.3), Signals (JB2.12)
CCLK: Connector (J3.26), Signals (JB1.92)
CSO_B: Connector (J3.25), Signals (JB1.88)
EN: Connector (J1.6), Signals (JB1.27)
HSWAPEN: Connector (J2.4), Signals (JB2.14)
INIT: Connector (J1.5), Signals (JB1.29 S2.1)
MISO: Connector (J3.27), Signals (JB1.94)
MISO2: Connector (J3.30), Signals (JB1.100)
MISO3: Connector (J3.29), Signals (JB1.98)
MOSI: Connector (J3.28), Signals (JB1.96)
PFI: Connector (J2.6), Signals (JB2.15)
PHY_AVDD: Signals (JB1.13), Ethernet (C2.2 J14.1)
PHY_DUP: Connector (J8.5), Signals (JB1.24)
PHY_L10: Connector (J8.4), Signals (JB1.18)
PHY_L100: Connector (J8.6), Signals (JB1.20)
PHY_L1000: Connector (J8.3), Signals (JB1.22)
PHY_LED_RX: Signals (JB1.28), Ethernet (J14.14)
PHY_LED_TX: Signals (JB1.26), Ethernet (J14.12)
PHY_MDI0_N: Signals (JB1.5), Ethernet (J14.3 R6.1)
PHY_MDI0_P: Signals (JB1.3), Ethernet (J14.2 R5.1)
PHY_MDI1_N: Signals (JB1.11), Ethernet (J14.5 R8.1)
PHY_MDI1_P: Signals (JB1.9), Ethernet (J14.4 R7.1)
PHY_MDI2_N: Signals (JB1.17), Ethernet (J14.7 R10.1)
PHY_MDI2_P: Signals (JB1.15), Ethernet (J14.6 R9.1)
PHY_MDI3_N: Signals (JB1.23), Ethernet (J14.9 R12.1)
PHY_MDI3_P: Signals (JB1.21), Ethernet (J14.8 R11.1)
RFUSE: Connector (J3.23), Signals (JB1.84)
SUSPEND: Connector (J3.18), Signals (JB1.78)
TCK: Connector (J5.6 J6.4), Signals (JB2.100)
TDI: Connector (J5.10 J6.2), Signals (JB2.96)
TDO: Connector (J5.8 J6.3), Signals (JB2.98)
TMS: Connector (J5.4 J6.1), Signals (JB2.94)
VBATT: Connector (J3.21), Signals (JB1.80)
VFS: Connector (J3.22), Signals (JB1.82)

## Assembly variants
TE0603-01: not fitted C4 J6 J12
